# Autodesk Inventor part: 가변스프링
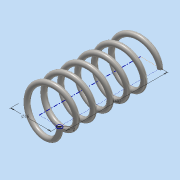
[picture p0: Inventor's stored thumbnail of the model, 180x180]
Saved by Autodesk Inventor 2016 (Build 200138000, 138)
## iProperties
Created: 2018-06
Part Number: 가변스프링
Material: 강철, 탄소
Document SubType Name: Modeling
Designer: 602-09
Density: 7.85 g/cm^3
Appearance: 반연마
Mass: 7.35983 g
Surface Area: 18.9964 cm^2
Volume: 0.937559 cm^3
Author: 602-09
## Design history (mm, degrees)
sketch "스케치1"
  geometry: L1 (0, 0)-(8, 0); L2 (8, 0)-(8, 33); L3 (8, 33)-(0, 33); L4 (0, 33)-(0, 0); C1 r 1 at (8, 0)
  constraints: 8 end point, 2 parallel, 1 centre point, 1 coincident, 1 horizontal, 1 perpendicular
  dimensions: "d0" = 2 diameter of C1; "d1" = 33 distance of L1.end L2.end (derived); "d2" = 16 diameter of L2 L4
feature "코일1" pitch "d3" = 10; turns "d5" = 6; dims "d4" = 33 (= d1), "d6" = 0, angle "d7" = 90 deg, angle "d8" = 90 deg, "d9" = 0, "d10" = 0
sketch "스케치2"
  geometry: L1 (-9, 0)-(-7, 0) reference; 1 further point
  constraints: 1 horizontal alignment
extrude "돌출1" cut sketch "스케치2" stored distance "d11" = 10; taper "d12" = 0 deg
node "작업 평면1"
sketch "스케치3"
  geometry: L1 (1, 0)-(-1, 0) reference; 1 further point
  constraints: 1 horizontal alignment
extrude "돌출2" cut sketch "스케치3" stored distance "d14" = 10; taper "d15" = 0 deg
node "솔리드1"
node "절단 모서리 투영1"
node "절단 모서리 투영2"
other parameters: "d13" = 90 deg
